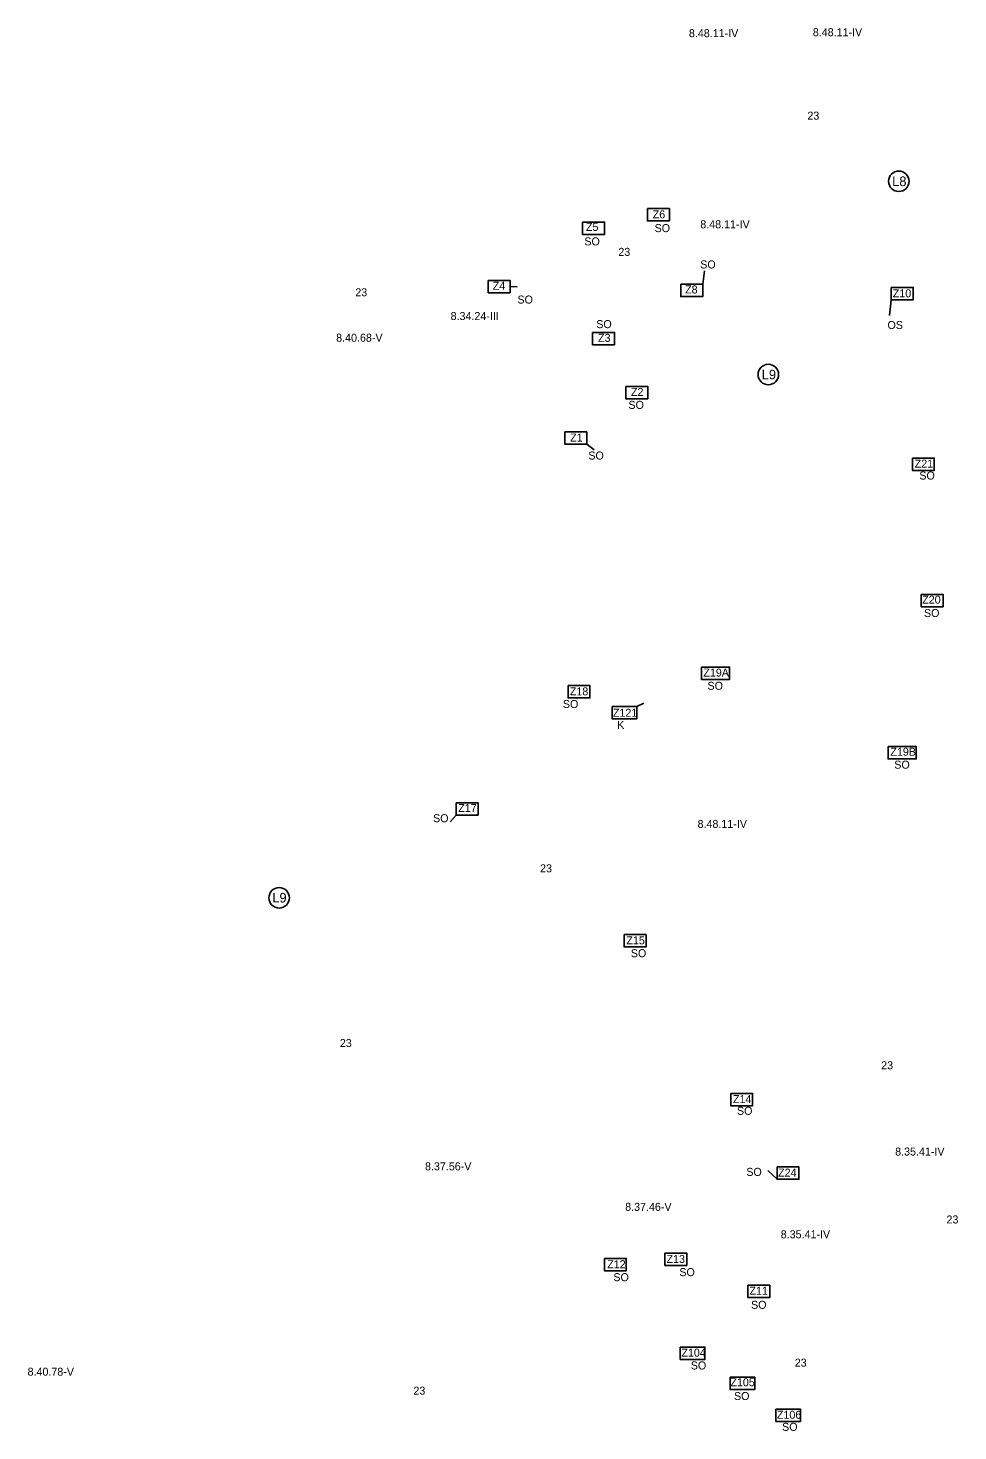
# Model space of a CAD drawing. Extents: x -450307 to -440553, y -1134449 to -1129789.
# Drawn here: x -443550 to -442388, y -1132114 to -1130361 of the extents above; entities that cross this region are included whole.
import ezdxf

# ---------------------------------------------------------------- set-up
doc = ezdxf.new("R2010")
doc.units = 0
for name, color, linetype in [('Vrstva 18', 7, 'Continuous'), ('Vrstva 28', 7, 'Continuous'), ('Vrstva 36', 7, 'Continuous')]:
    doc.layers.add(name, color=color, linetype=linetype)

msp = doc.modelspace()

# ---------------------------------------------------------------- linework, layer by layer
at = {"layer": 'Vrstva 18'}
for p, q in [((-442704.6, -1130664.6), (-442706.7, -1130681.5)), ((-442947.3, -1130684.5), (-442938.5, -1130684.6)), ((-442473.2, -1130720.8), (-442471.1, -1130700.9)), ((-442851.5, -1130881.4), (-442842.3, -1130888.4)), ((-442789.2, -1131209.2), (-442780.3, -1131205)), ((-443014.7, -1131344.8), (-443022.4, -1131353.5)), ((-442613.7, -1131800), (-442625.4, -1131789))]:
    msp.add_line(p, q, dxfattribs=at)
for points in [[(-442775.7, -1130587.1), (-442748.3, -1130587.1), (-442748.3, -1130602.5), (-442775.7, -1130602.5)], [(-442856.8, -1130603.8), (-442829.4, -1130603.8), (-442829.4, -1130619.2), (-442856.8, -1130619.2)], [(-442974.7, -1130676.8), (-442947.3, -1130676.8), (-442947.3, -1130692.2), (-442974.7, -1130692.2)], [(-442734.1, -1130681.5), (-442706.7, -1130681.5), (-442706.7, -1130696.9), (-442734.1, -1130696.9)], [(-442471.1, -1130685.5), (-442443.7, -1130685.5), (-442443.7, -1130700.9), (-442471.1, -1130700.9)], [(-442844.2, -1130741.8), (-442816.9, -1130741.8), (-442816.9, -1130757.2), (-442844.2, -1130757.2)], [(-442802.8, -1130809.3), (-442775.4, -1130809.3), (-442775.4, -1130824.7), (-442802.8, -1130824.7)], [(-442878.9, -1130866.1), (-442851.5, -1130866.1), (-442851.5, -1130881.4), (-442878.9, -1130881.4)], [(-442444.7, -1130898.7), (-442417.3, -1130898.7), (-442417.3, -1130914.1), (-442444.7, -1130914.1)], [(-442433.7, -1131069.2), (-442406.4, -1131069.2), (-442406.4, -1131084.6), (-442433.7, -1131084.6)], [(-442708.4, -1131160), (-442673.1, -1131160), (-442673.1, -1131175.4), (-442708.4, -1131175.4)], [(-442874.9, -1131183), (-442847.6, -1131183), (-442847.6, -1131198.4), (-442874.9, -1131198.4)], [(-442819.9, -1131209.2), (-442789.2, -1131209.2), (-442789.2, -1131224.6), (-442819.9, -1131224.6)], [(-442475.1, -1131259.2), (-442439.9, -1131259.2), (-442439.9, -1131274.6), (-442475.1, -1131274.6)], [(-443014.7, -1131329.4), (-442987.3, -1131329.4), (-442987.3, -1131344.8), (-443014.7, -1131344.8)], [(-442804.9, -1131494.2), (-442777.5, -1131494.2), (-442777.5, -1131509.6), (-442804.9, -1131509.6)], [(-442671.7, -1131692.6), (-442644.4, -1131692.6), (-442644.4, -1131708), (-442671.7, -1131708)], [(-442613.7, -1131784.6), (-442586.4, -1131784.6), (-442586.4, -1131800), (-442613.7, -1131800)], [(-442753.9, -1131892.2), (-442726.6, -1131892.2), (-442726.6, -1131907.6), (-442753.9, -1131907.6)], [(-442829.6, -1131898.8), (-442802.2, -1131898.8), (-442802.2, -1131914.2), (-442829.6, -1131914.2)], [(-442650.3, -1131932.3), (-442622.9, -1131932.3), (-442622.9, -1131947.7), (-442650.3, -1131947.7)], [(-442734.8, -1132009.7), (-442704, -1132009.7), (-442704, -1132025.1), (-442734.8, -1132025.1)], [(-442672.3, -1132047.4), (-442641.6, -1132047.4), (-442641.6, -1132062.8), (-442672.3, -1132062.8)], [(-442615.4, -1132087.1), (-442584.7, -1132087.1), (-442584.7, -1132102.5), (-442615.4, -1132102.5)]]:
    msp.add_lwpolyline(points, close=True, dxfattribs=at)
at = {"layer": 'Vrstva 36'}
for centre in [(-442461.7, -1130552.9), (-442624.7, -1130794.4), (-443236, -1131448.2)]:
    msp.add_circle(centre, 12.8, dxfattribs=at)

# ---------------------------------------------------------------- texts
at = {"layer": 'Vrstva 18'}
for s, p in [('Z6', (-442769.2, -1130599.2)), ('Z5', (-442852.6, -1130614.9)), ('SO', (-442766.8, -1130616.4)), ('SO', (-442854.6, -1130633)), ('SO', (-442709.8, -1130661.8)), ('Z4', (-442969.1, -1130688.5)), ('Z8', (-442728.7, -1130693.1)), ('SO', (-442938.2, -1130705.7)), ('Z10', (-442469.2, -1130697.9)), ('SO', (-442839.7, -1130736.4)), ('OS', (-442475.8, -1130737.5)), ('Z3', (-442837.5, -1130753.5)), ('Z2', (-442796.3, -1130821.1)), ('SO', (-442799.5, -1130837.3)), ('Z1', (-442872.3, -1130878.1)), ('SO', (-442849.6, -1130900.6)), ('Z21', (-442441.8, -1130910.7)), ('SO', (-442436, -1130925.6)), ('Z20', (-442432.4, -1131080.7)), ('SO', (-442430.2, -1131097.4)), ('Z19A', (-442705.9, -1131171.8)), ('Z18', (-442872.7, -1131195.3)), ('SO', (-442700.7, -1131188.3)), ('SO', (-442881.4, -1131211.1)), ('Z121', (-442818.9, -1131222)), ('K', (-442813.6, -1131237.2)), ('Z19B', (-442472.2, -1131270.7)), ('SO', (-442467.3, -1131286.9)), ('Z17', (-443012.2, -1131341)), ('SO', (-443043.6, -1131353.8)), ('Z15', (-442802.1, -1131506.4)), ('SO', (-442796.5, -1131522.5)), ('Z14', (-442668.9, -1131704.8)), ('SO', (-442663.9, -1131719.4)), ('SO', (-442652.2, -1131795.7)), ('Z24', (-442612.5, -1131796.6)), ('Z13', (-442751.9, -1131904.5)), ('Z12', (-442826, -1131911.1)), ('SO', (-442735.9, -1131921)), ('SO', (-442818.3, -1131927.3)), ('Z11', (-442648.3, -1131944.2)), ('SO', (-442646.3, -1131961.8)), ('Z104', (-442733.3, -1132021.6)), ('SO', (-442721.6, -1132037.6)), ('Z105', (-442672.1, -1132058.6)), ('SO', (-442667.6, -1132075.8)), ('Z106', (-442614, -1132099.2)), ('SO', (-442607.5, -1132114.3))]:
    msp.add_text(s, height=10, dxfattribs=at).set_placement(p)
at = {"layer": 'Vrstva 28'}
for s, p in [('8.48.11-IV', (-442723.9, -1130372.8)), ('8.48.11-IV', (-442569.1, -1130371.6)), ('23', (-442575.9, -1130475.9)), ('8.48.11-IV', (-442709.7, -1130611.6)), ('23', (-442812.1, -1130646.1)), ('23', (-443140.8, -1130696.6)), ('8.34.24-III', (-443021.7, -1130726.3)), ('8.40.68-V', (-443164.7, -1130753.4)), ('8.48.11-IV', (-442713.1, -1131360.9)), ('23', (-442909.9, -1131416.4)), ('23', (-443160.1, -1131634.7)), ('23', (-442483.7, -1131662.5)), ('8.35.41-IV', (-442466.2, -1131770.3)), ('8.37.56-V', (-443053.7, -1131788.8)), ('8.37.46-V', (-442803.6, -1131839.4)), ('23', (-442402.1, -1131855.2)), ('8.35.41-IV', (-442609.2, -1131873.7)), ('8.40.78-V', (-443550.3, -1132045.4)), ('23', (-442591.7, -1132034.1)), ('23', (-443068.2, -1132069.1))]:
    msp.add_text(s, height=10, dxfattribs=at).set_placement(p)
at = {"layer": 'Vrstva 36'}
for s, p in [('L8', (-442469.9, -1130558.9)), ('L9', (-442632.9, -1130800.4)), ('L9', (-443244.5, -1131454.1))]:
    msp.add_text(s, height=12, dxfattribs=at).set_placement(p)

doc.saveas('drawing.dxf')
